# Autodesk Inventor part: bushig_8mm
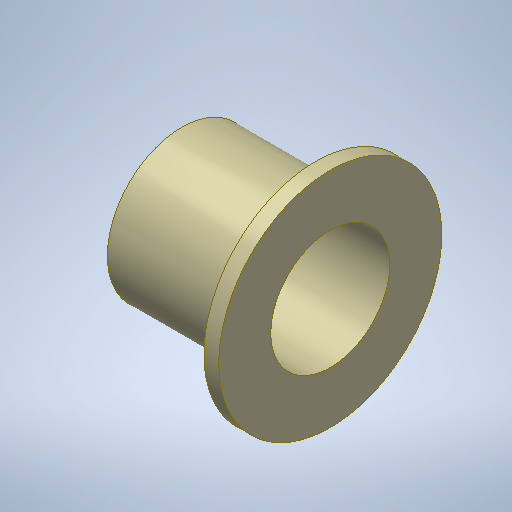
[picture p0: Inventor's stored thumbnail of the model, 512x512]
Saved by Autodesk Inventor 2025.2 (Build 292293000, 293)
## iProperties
Created: 2025-04
Part Number: bushig_8mm
Material: Nylon 6
Document SubType Name: Modeling
Designer: BennF
Density: 1.12 g/cm^3
Appearance: Nylon 6
Author: BennF
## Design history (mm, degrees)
sketch "Sketch2"
  geometry: L1 (-10, 4)-(-10, 7.5); L2 (-10, 7.5)-(-9, 7.5); L3 (-9, 7.5)-(-9, 5); L4 (-9, 5)-(0, 5); L5 (0, 5)-(0, 4); L6 (0, 4)-(-10, 4); L7 (0, 0)-(-10, 0)
  constraints: 15 end point, 5 perpendicular, 2 vertical alignment, 1 horizontal, 1 vertical
  dimensions: "d0" = 8 diameter of L6 L7; "d1" = 10 diameter of L4 L7; "d2" = 15 diameter of L2 L7; "d3" = 1 distance of L1.end L2.end; "d4" = 10 distance of L5.end L1.start
revolve "Revolution1" sketch "Sketch2" stored, may be unused: angle "d5" = 90 deg
body "Solid1"
